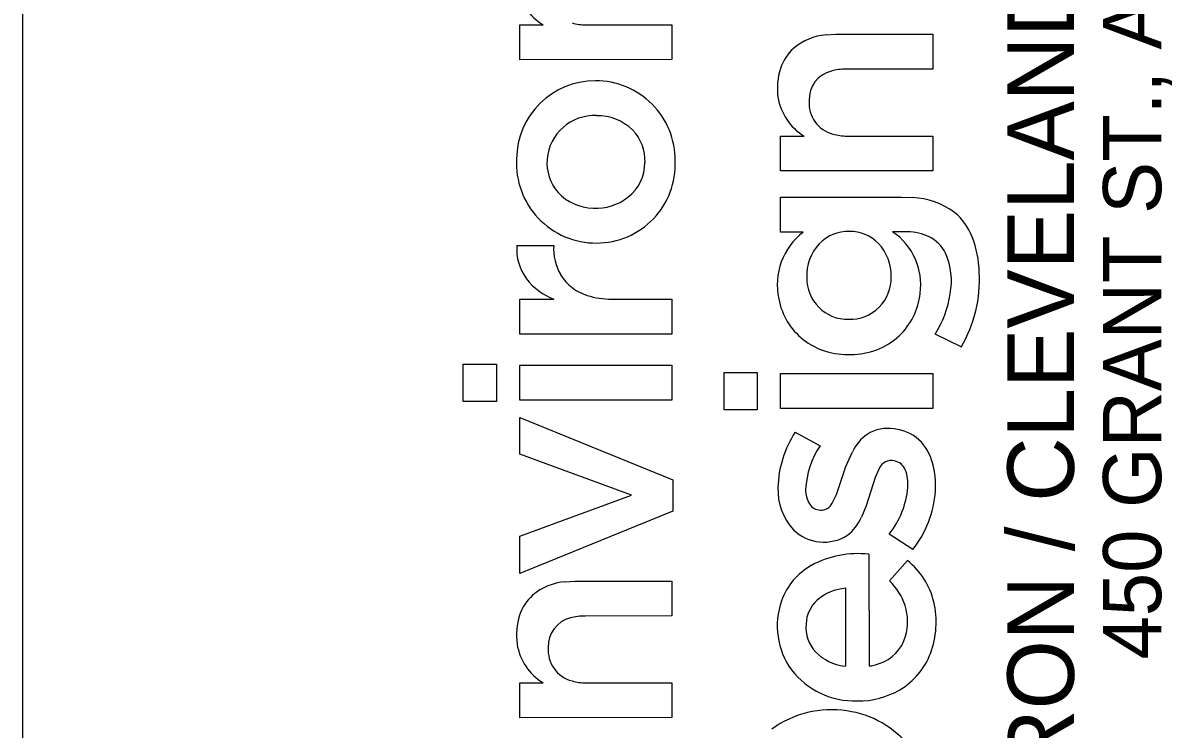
# Model space of a CAD drawing. Extents: x -0.3 to 34, y 0 to 22.
# Drawn here: x 32 to 32.984, y 2.778 to 3.382 of the extents above; entities that cross this region are included whole.
import ezdxf

# ---------------------------------------------------------------- set-up
doc = ezdxf.new("R2010")
doc.units = 0
doc.layers.add('GM_X_Adjacent_County_Text', color=7, linetype='Continuous')
doc.layers.add('GM_X_County', color=7, linetype='Continuous')

msp = doc.modelspace()

# ---------------------------------------------------------------- linework, layer by layer
at = {"layer": 'GM_X_Adjacent_County_Text'}
for p, q in [((32.42542, 3.38066), (32.44552, 3.38071)), ((32.42542, 3.35086), (32.42542, 3.38066)), ((32.48222, 3.38071), (32.55569, 3.38071)), ((32.55569, 3.38071), (32.55571, 3.35096)), ((32.68784, 3.3722), (32.69634, 3.37266)), ((32.69634, 3.37266), (32.77916, 3.37266)), ((32.77916, 3.37266), (32.77917, 3.34287)), ((32.55571, 3.35096), (32.42542, 3.35086)), ((32.77917, 3.34287), (32.70485, 3.3428)), ((32.64888, 3.2855), (32.66897, 3.28555)), ((32.64888, 3.25569), (32.64888, 3.2855)), ((32.70568, 3.28555), (32.77915, 3.28555)), ((32.77915, 3.28555), (32.77917, 3.25579)), ((32.77917, 3.25579), (32.64888, 3.25569)), ((32.6489, 3.20336), (32.64889, 3.23322)), ((32.64889, 3.23322), (32.75236, 3.23322)), ((32.75236, 3.23322), (32.76191, 3.23285)), ((32.66836, 3.20336), (32.6489, 3.20336)), ((32.75763, 3.20356), (32.74487, 3.20361)), ((32.42299, 3.19193), (32.45454, 3.19193)), ((32.42542, 3.14577), (32.45473, 3.14579)), ((32.42542, 3.11593), (32.42542, 3.14577)), ((32.50413, 3.14581), (32.55571, 3.14573)), ((32.55571, 3.14573), (32.55565, 3.11593)), ((32.55565, 3.11593), (32.42542, 3.11593)), ((32.8036, 3.10491), (32.7812, 3.11598)), ((32.37705, 3.05818), (32.37705, 3.09026)), ((32.37705, 3.09026), (32.40543, 3.09026)), ((32.40543, 3.09026), (32.40543, 3.05818)), ((32.42542, 3.05942), (32.42542, 3.08928)), ((32.42542, 3.08928), (32.55571, 3.08928)), ((32.55571, 3.08928), (32.55571, 3.05942)), ((32.60051, 3.05111), (32.60051, 3.08319)), ((32.60051, 3.08319), (32.62889, 3.08319)), ((32.62889, 3.08319), (32.62889, 3.05111)), ((32.64888, 3.05234), (32.64888, 3.0822)), ((32.64888, 3.0822), (32.77917, 3.0822)), ((32.77917, 3.0822), (32.77917, 3.05234)), ((32.40543, 3.05818), (32.37705, 3.05818)), ((32.55571, 3.05942), (32.42542, 3.05942)), ((32.62889, 3.05111), (32.60051, 3.05111)), ((32.77917, 3.05234), (32.64888, 3.05234)), ((32.42542, 3.01327), (32.42542, 3.0446)), ((32.42542, 3.0446), (32.5567, 2.9913)), ((32.66151, 3.03207), (32.68268, 3.02025)), ((32.52117, 2.97798), (32.42542, 3.01327)), ((32.70483, 3.00258), (32.71036, 3.01526)), ((32.69675, 2.97868), (32.70483, 3.00258)), ((32.72985, 2.9933), (32.72213, 2.96882)), ((32.73342, 3.00101), (32.72985, 2.9933)), ((32.5567, 2.9913), (32.5567, 2.96441)), ((32.42542, 2.94294), (32.52117, 2.97798)), ((32.69299, 2.97117), (32.69675, 2.97868)), ((32.5567, 2.96441), (32.42542, 2.91086)), ((32.72213, 2.96882), (32.71822, 2.95921)), ((32.42542, 2.91086), (32.42542, 2.94294)), ((32.76214, 2.93141), (32.74198, 2.94469)), ((32.72453, 2.92747), (32.72463, 2.83195)), ((32.74228, 2.90465), (32.75768, 2.922)), ((32.46439, 2.90397), (32.47289, 2.90443)), ((32.47289, 2.90443), (32.55571, 2.90443)), ((32.55571, 2.90443), (32.55571, 2.87465)), ((32.70489, 2.83182), (32.70489, 2.89834)), ((32.55571, 2.87465), (32.4814, 2.87457)), ((32.70361, 2.83165), (32.70489, 2.83182)), ((32.42542, 2.81728), (32.44552, 2.81733)), ((32.42542, 2.78747), (32.42542, 2.81728)), ((32.48222, 2.81733), (32.55569, 2.81733)), ((32.55569, 2.81733), (32.55571, 2.78756)), ((32.55571, 2.78756), (32.42542, 2.78747))]:
    msp.add_line(p, q, dxfattribs=at)
for points in [[(32.42542, 3.35086), (32.42542, 3.38066), (32.44552, 3.38071)], [(32.48222, 3.38071), (32.55569, 3.38071), (32.55571, 3.35096), (32.42542, 3.35086)], [(32.68784, 3.3722), (32.69634, 3.37266), (32.77916, 3.37266), (32.77917, 3.34287), (32.70485, 3.3428)], [(32.64888, 3.25569), (32.64888, 3.2855), (32.66897, 3.28555)], [(32.70568, 3.28555), (32.77915, 3.28555), (32.77917, 3.25579), (32.64888, 3.25569)], [(32.66836, 3.20336), (32.6489, 3.20336), (32.64889, 3.23322), (32.75236, 3.23322), (32.76191, 3.23285)], [(32.75763, 3.20356), (32.74487, 3.20361)], [(32.42299, 3.19193), (32.45454, 3.19193)], [(32.50413, 3.14581), (32.55571, 3.14573), (32.55565, 3.11593), (32.42542, 3.11593)], [(32.42542, 3.11593), (32.42542, 3.14577), (32.45473, 3.14579)], [(32.8036, 3.10491), (32.7812, 3.11598)], [(32.66151, 3.03207), (32.68268, 3.02025)], [(32.69299, 2.97117), (32.69675, 2.97868), (32.70483, 3.00258), (32.71036, 3.01526)], [(32.73342, 3.00101), (32.72985, 2.9933), (32.72213, 2.96882), (32.71822, 2.95921)], [(32.76214, 2.93141), (32.74198, 2.94469)], [(32.72453, 2.92747), (32.72463, 2.83195)], [(32.74228, 2.90465), (32.75768, 2.922)], [(32.46439, 2.90397), (32.47289, 2.90443), (32.55571, 2.90443), (32.55571, 2.87465), (32.4814, 2.87457)], [(32.70361, 2.83165), (32.70489, 2.83182), (32.70489, 2.89834)], [(32.42542, 2.78747), (32.42542, 2.81728), (32.44552, 2.81733)], [(32.48222, 2.81733), (32.55569, 2.81733), (32.55571, 2.78756), (32.42542, 2.78747)]]:
    msp.add_lwpolyline(points, dxfattribs=at)
for points in [[(32.37705, 3.05818), (32.37705, 3.09026), (32.40543, 3.09026), (32.40543, 3.05818)], [(32.42542, 3.05942), (32.42542, 3.08928), (32.55571, 3.08928), (32.55571, 3.05942)], [(32.60051, 3.05111), (32.60051, 3.08319), (32.62889, 3.08319), (32.62889, 3.05111)], [(32.64888, 3.05234), (32.64888, 3.0822), (32.77917, 3.0822), (32.77917, 3.05234)], [(32.42542, 2.91086), (32.42542, 2.94294), (32.52117, 2.97798), (32.42542, 3.01327), (32.42542, 3.0446), (32.5567, 2.9913), (32.5567, 2.96441)]]:
    msp.add_lwpolyline(points, close=True, dxfattribs=at)
for centre, radius, start, end in [((32.47027, 3.42141), 0.04763, 188.96462, 238.69865), ((32.47027, 3.42141), 0.04763, 188.96462, 238.69865), ((32.48183, 3.42286), 0.04215, 254.08913, 270.52838), ((32.48183, 3.42286), 0.04215, 254.08913, 270.52838), ((32.69216, 3.32251), 0.04988, 94.97056, 130.22484), ((32.69216, 3.32251), 0.04988, 94.97056, 130.22484), ((32.68694, 3.33085), 0.04016, 132.22383, 161.68229), ((32.68694, 3.33085), 0.04016, 132.22383, 161.68229), ((32.70217, 3.32642), 0.05602, 162.27398, 187.79173), ((32.70217, 3.32642), 0.05602, 162.27398, 187.79173), ((32.69828, 3.31689), 0.02498, 103.68683, 182.21395), ((32.69828, 3.31689), 0.02498, 103.68683, 182.21395), ((32.70453, 3.29679), 0.04601, 89.60515, 105.33026), ((32.70453, 3.29679), 0.04601, 89.60515, 105.33026), ((32.49014, 3.26543), 0.0674, 89.84756, 179.64047), ((32.49014, 3.26543), 0.0674, 89.84756, 179.64047), ((32.49057, 3.26474), 0.0681, 359.54009, 90.21138), ((32.49057, 3.26474), 0.0681, 359.54009, 90.21138), ((32.69372, 3.32624), 0.04763, 188.96462, 238.69865), ((32.69372, 3.32624), 0.04763, 188.96462, 238.69865), ((32.7008, 3.31381), 0.02757, 175.58441, 255.13816), ((32.7008, 3.31381), 0.02757, 175.58441, 255.13816), ((32.48923, 3.26263), 0.0404, 87.04809, 175.57259), ((32.48923, 3.26263), 0.0404, 87.04809, 175.57259), ((32.49204, 3.25999), 0.04299, 45.84264, 90.98008), ((32.49204, 3.25999), 0.04299, 45.84264, 90.98008), ((32.49458, 3.26421), 0.03821, 357.88569, 44.15902), ((32.49458, 3.26421), 0.03821, 357.88569, 44.15902), ((32.70529, 3.32769), 0.04215, 254.08913, 270.52838), ((32.70529, 3.32769), 0.04215, 254.08913, 270.52838), ((32.49083, 3.26209), 0.06819, 176.8344, 270.40384), ((32.49083, 3.26209), 0.06819, 176.8344, 270.40384), ((32.48729, 3.2625), 0.03848, 175.15378, 221.14706), ((32.48729, 3.2625), 0.03848, 175.15378, 221.14706), ((32.49123, 3.26139), 0.06749, 270.06243, 2.37759), ((32.49123, 3.26139), 0.06749, 270.06243, 2.37759), ((32.49446, 3.26318), 0.0383, 308.28936, 359.43468), ((32.49446, 3.26318), 0.0383, 308.28936, 359.43468), ((32.48919, 3.26607), 0.04228, 223.09994, 268.80895), ((32.48919, 3.26607), 0.04228, 223.09994, 268.80895), ((32.49096, 3.2679), 0.04418, 266.56515, 308.06078), ((32.49096, 3.2679), 0.04418, 266.56515, 308.06078), ((32.75907, 3.16789), 0.06503, 53.40344, 87.49062), ((32.75907, 3.16789), 0.06503, 53.40344, 87.49062), ((32.76517, 3.18039), 0.05141, 21.60748, 50.5577), ((32.76517, 3.18039), 0.05141, 21.60748, 50.5577), ((32.70292, 3.15813), 0.05692, 127.37482, 192.22468), ((32.70292, 3.15813), 0.05692, 127.37482, 192.22468), ((32.70693, 3.16927), 0.0346, 88.47302, 136.42562), ((32.70693, 3.16927), 0.0346, 88.47302, 136.42562), ((32.70814, 3.16963), 0.03424, 44.27195, 90.47623), ((32.70814, 3.16963), 0.03424, 44.27195, 90.47623), ((32.71421, 3.15829), 0.05472, 352.1125, 55.92295), ((32.71421, 3.15829), 0.05472, 352.1125, 55.92295), ((32.75666, 3.15725), 0.04633, 65.01687, 88.8011), ((32.75666, 3.15725), 0.04633, 65.01687, 88.8011), ((32.7626, 3.17155), 0.03085, 26.26808, 63.80301), ((32.7626, 3.17155), 0.03085, 26.26808, 63.80301), ((32.73069, 3.16714), 0.08835, 1.15143, 21.3627), ((32.73069, 3.16714), 0.08835, 1.15143, 21.3627), ((32.46616, 3.18882), 0.04329, 175.87313, 216.34747), ((32.46616, 3.18882), 0.04329, 175.87313, 216.34747), ((32.50087, 3.18948), 0.04639, 176.9688, 209.60636), ((32.50087, 3.18948), 0.04639, 176.9688, 209.60636), ((32.71141, 3.16602), 0.0401, 137.46739, 182.33237), ((32.71141, 3.16602), 0.0401, 137.46739, 182.33237), ((32.70368, 3.166), 0.03996, 358.57141, 43.53765), ((32.70368, 3.166), 0.03996, 358.57141, 43.53765), ((32.73565, 3.16154), 0.05953, 349.30734, 23.43071), ((32.73565, 3.16154), 0.05953, 349.30734, 23.43071), ((32.47466, 3.19716), 0.05511, 218.09809, 248.7907), ((32.47466, 3.19716), 0.05511, 218.09809, 248.7907), ((32.49514, 3.18814), 0.04079, 211.94466, 253.2028), ((32.49514, 3.18814), 0.04079, 211.94466, 253.2028), ((32.70645, 3.1637), 0.03511, 178.88208, 271.08374), ((32.70645, 3.1637), 0.03511, 178.88208, 271.08374), ((32.70818, 3.16404), 0.03546, 268.27882, 1.55016), ((32.70818, 3.16404), 0.03546, 268.27882, 1.55016), ((32.70538, 3.16244), 0.11383, 329.6388, 3.25998), ((32.70538, 3.16244), 0.11383, 329.6388, 3.25998), ((32.70988, 3.15708), 0.05887, 313.74196, 353.8554), ((32.70988, 3.15708), 0.05887, 313.74196, 353.8554), ((32.70738, 3.16334), 0.08771, 327.31495, 351.57478), ((32.70738, 3.16334), 0.08771, 327.31495, 351.57478), ((32.50465, 3.2165), 0.07069, 252.46555, 269.57296), ((32.50465, 3.2165), 0.07069, 252.46555, 269.57296), ((32.70463, 3.15696), 0.05837, 190.75182, 231.28919), ((32.70463, 3.15696), 0.05837, 190.75182, 231.28919), ((32.70632, 3.16112), 0.06269, 232.46061, 272.59022), ((32.70632, 3.16112), 0.06269, 232.46061, 272.59022), ((32.70954, 3.15901), 0.06051, 269.6361, 312.70877), ((32.70954, 3.15901), 0.06051, 269.6361, 312.70877), ((32.73636, 2.98258), 0.08973, 146.53104, 178.7571), ((32.73636, 2.98258), 0.08973, 146.53104, 178.7571), ((32.7406, 3.0026), 0.03263, 80.17192, 122.51969), ((32.7406, 3.0026), 0.03263, 80.17192, 122.51969), ((32.74278, 2.99824), 0.03667, 47.79344, 84.68918), ((32.74278, 2.99824), 0.03667, 47.79344, 84.68918), ((32.74661, 2.99713), 0.04053, 125.51182, 153.41595), ((32.74661, 2.99713), 0.04053, 125.51182, 153.41595), ((32.73788, 2.9946), 0.04267, 14.9966, 46.20632), ((32.73788, 2.9946), 0.04267, 14.9966, 46.20632), ((32.74519, 2.9789), 0.07495, 146.51121, 176.91007), ((32.74519, 2.9789), 0.07495, 146.51121, 176.91007), ((32.74384, 2.99631), 0.01143, 76.66094, 155.7053), ((32.74384, 2.99631), 0.01143, 76.66094, 155.7053), ((32.74397, 2.99511), 0.01256, 21.5098, 78.52618), ((32.74397, 2.99511), 0.01256, 21.5098, 78.52618), ((32.71044, 2.98674), 0.07121, 355.83062, 15.39138), ((32.71044, 2.98674), 0.07121, 355.83062, 15.39138), ((32.72592, 2.98766), 0.03209, 354.57264, 22.06805), ((32.72592, 2.98766), 0.03209, 354.57264, 22.06805), ((32.69666, 2.98238), 0.05005, 177.53659, 222.79318), ((32.69666, 2.98238), 0.05005, 177.53659, 222.79318), ((32.6931, 2.98233), 0.02276, 178.47474, 211.08679), ((32.6931, 2.98233), 0.02276, 178.47474, 211.08679), ((32.68248, 2.99149), 0.0757, 321.81101, 354.79685), ((32.68248, 2.99149), 0.0757, 321.81101, 354.79685), ((32.68952, 2.9882), 0.09219, 321.9777, 355.87384), ((32.68952, 2.9882), 0.09219, 321.9777, 355.87384), ((32.68331, 2.9767), 0.01148, 212.23676, 268.37769), ((32.68331, 2.9767), 0.01148, 212.23676, 268.37769), ((32.68342, 2.97589), 0.01067, 267.71603, 333.73375), ((32.68342, 2.97589), 0.01067, 267.71603, 333.73375), ((32.68098, 2.9758), 0.04077, 308.08772, 335.98736), ((32.68098, 2.9758), 0.04077, 308.08772, 335.98736), ((32.68599, 2.97535), 0.0375, 225.98539, 302.47965), ((32.68599, 2.97535), 0.0375, 225.98539, 302.47965), ((32.7152, 2.84414), 0.08384, 83.61499, 118.28755), ((32.7152, 2.84414), 0.08384, 83.61499, 118.28755), ((32.70239, 2.86906), 0.05583, 118.83082, 160.62438), ((32.70239, 2.86906), 0.05583, 118.83082, 160.62438), ((32.71744, 2.87167), 0.06443, 13.53365, 51.36148), ((32.71744, 2.87167), 0.06443, 13.53365, 51.36148), ((32.46871, 2.85428), 0.04988, 94.96958, 130.22249), ((32.46871, 2.85428), 0.04988, 94.96958, 130.22249), ((32.70378, 2.86556), 0.05486, 19.03571, 45.44059), ((32.70378, 2.86556), 0.05486, 19.03571, 45.44059), ((32.70785, 2.85609), 0.04235, 94.00805, 130.88169), ((32.70785, 2.85609), 0.04235, 94.00805, 130.88169), ((32.46348, 2.86263), 0.04015, 132.22192, 161.68183), ((32.46348, 2.86263), 0.04015, 132.22192, 161.68183), ((32.71041, 2.86612), 0.06437, 160.52012, 215.78311), ((32.71041, 2.86612), 0.06437, 160.52012, 215.78311), ((32.70048, 2.86628), 0.02985, 132.98507, 177.179), ((32.70048, 2.86628), 0.02985, 132.98507, 177.179), ((32.70635, 2.86921), 0.07579, 339.3542, 13.37853), ((32.70635, 2.86921), 0.07579, 339.3542, 13.37853), ((32.47872, 2.85819), 0.05601, 162.27355, 187.79185), ((32.47872, 2.85819), 0.05601, 162.27355, 187.79185), ((32.48108, 2.82856), 0.04601, 89.60494, 105.3284), ((32.48108, 2.82856), 0.04601, 89.60494, 105.3284), ((32.71069, 2.8697), 0.047, 344.60586, 17.007), ((32.71069, 2.8697), 0.047, 344.60586, 17.007), ((32.47482, 2.84867), 0.02498, 103.68646, 182.21874), ((32.47482, 2.84867), 0.02498, 103.68646, 182.21874), ((32.7017, 2.86503), 0.03115, 175.00126, 223.28301), ((32.7017, 2.86503), 0.03115, 175.00126, 223.28301), ((32.7224, 2.86715), 0.03504, 288.00773, 343.55078), ((32.7224, 2.86715), 0.03504, 288.00773, 343.55078), ((32.47026, 2.85802), 0.04762, 188.96199, 238.70369), ((32.47026, 2.85802), 0.04762, 188.96199, 238.70369), ((32.47735, 2.84558), 0.02756, 175.58538, 255.14386), ((32.47735, 2.84558), 0.02756, 175.58538, 255.14386), ((32.70891, 2.87363), 0.04231, 225.06188, 262.79738), ((32.70891, 2.87363), 0.04231, 225.06188, 262.79738), ((32.71894, 2.8652), 0.0626, 300.94269, 338.73225), ((32.71894, 2.8652), 0.0626, 300.94269, 338.73225), ((32.71253, 2.87054), 0.06872, 217.74516, 271.65431), ((32.71253, 2.87054), 0.06872, 217.74516, 271.65431), ((32.72474, 2.85216), 0.02021, 269.7003, 294.8711), ((32.72474, 2.85216), 0.02021, 269.7003, 294.8711), ((32.48183, 2.85948), 0.04215, 254.09162, 270.52835), ((32.48183, 2.85948), 0.04215, 254.09162, 270.52835), ((32.71549, 2.87241), 0.07056, 269.20477, 300.33412), ((32.71549, 2.87241), 0.07056, 269.20477, 300.33412), ((32.69229, 2.70792), 0.08641, 81.19402, 125.99844), ((32.69229, 2.70792), 0.08641, 81.19402, 125.99844), ((32.69458, 2.71132), 0.08272, 37.85208, 82.40204), ((32.69458, 2.71132), 0.08272, 37.85208, 82.40204)]:
    msp.add_arc(centre, radius, start, end, dxfattribs=at)
at = {"layer": 'GM_X_County'}
msp.add_line((32, 0.5), (32, 21.5), dxfattribs=at)

# ---------------------------------------------------------------- texts
at = {"layer": 'GM_X_Adjacent_County_Text'}
for s, height, p in [('450 GRANT ST., AKRON, OH  44311', 0.0498462, (32.97489, 2.83738)), ('AKRON / CLEVELAND / COLUMBUS', 0.056969, (32.90012, 2.638))]:
    msp.add_text(s, height=height, rotation=90, dxfattribs=at).set_placement(p)

doc.saveas('drawing.dxf')
